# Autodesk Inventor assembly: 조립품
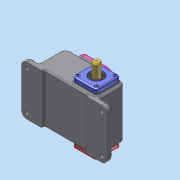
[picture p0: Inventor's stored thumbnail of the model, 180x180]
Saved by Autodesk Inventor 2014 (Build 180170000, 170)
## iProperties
Created: 2026-07
Part Number: 조립품
Document SubType Name: Assembly
Designer: dg
Author: dg
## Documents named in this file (14)
- C:\Users\dg\Desktop\660703V1007\조립품.iam
- C:\Users\dg\Desktop\660703V1007\가져온 구성요소\본체\본체.ipt
- C:\Users\dg\Desktop\660703V1007\가져온 구성요소\6각 구멍붙이 볼트 M4x10\6각 구멍붙이 볼트 M4x10.ipt
- C:\Users\dg\Desktop\660703V1007\가져온 구성요소\6각 구멍붙이 볼트 M5x10\6각 구멍붙이 볼트 M5x10.ipt
- C:\Users\dg\Desktop\660703V1007\가져온 구성요소\뒷커버\뒷커버.ipt
- C:\Users\dg\Desktop\660703V1007\가져온 구성요소\앞커버\앞커버.ipt
- C:\Users\dg\Desktop\660703V1007\가져온 구성요소\오일 실 17 32 8\오일 실 17 32 8.ipt
- C:\Users\dg\Desktop\660703V1007\가져온 구성요소\웜 샤프트\웜 샤프트.ipt
- C:\Users\dg\Desktop\660703V1007\가져온 구성요소\웜 휠 커버\웜 휠 커버.ipt
- C:\Users\dg\Desktop\660703V1007\가져온 구성요소\웜 휠\웜 휠.ipt
- C:\Users\dg\Desktop\660703V1007\가져온 구성요소\축\축.ipt
- C:\Users\dg\Desktop\660703V1007\가져온 구성요소\칼라\칼라.ipt
- C:\Users\dg\Desktop\660703V1007\가져온 구성요소\테이퍼 롤러 베어링 30203\테이퍼 롤러 베어링 30203.ipt
- C:\Users\dg\Desktop\660703V1007\가져온 구성요소\평행 키 5x5x16\평행 키 5x5x16.ipt
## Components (12 placed, 2 different names)
1. 6각 구멍붙이 볼트 M5x10:1
2. 6각 구멍붙이 볼트 M5x10:2
3. 6각 구멍붙이 볼트 M5x10:3
4. 6각 구멍붙이 볼트 M5x10:4
5. 6각 구멍붙이 볼트 M4x10:1
6. 6각 구멍붙이 볼트 M4x10:2
7. 6각 구멍붙이 볼트 M4x10:3
8. 6각 구멍붙이 볼트 M4x10:4
9. 6각 구멍붙이 볼트 M4x10:5
10. 6각 구멍붙이 볼트 M4x10:6
11. 6각 구멍붙이 볼트 M4x10:7
12. 6각 구멍붙이 볼트 M4x10:8
